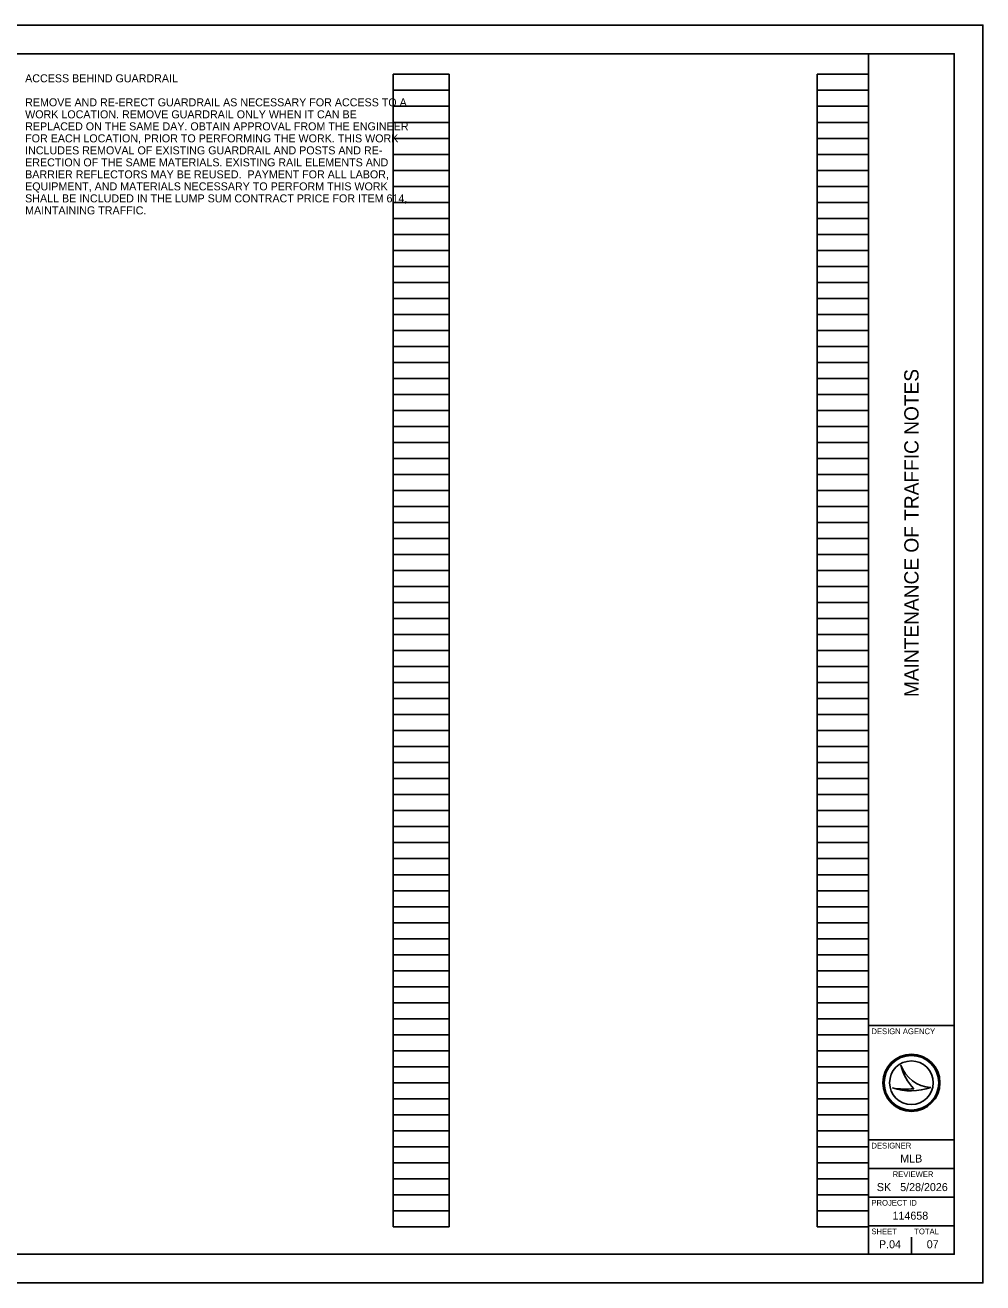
# Model space of a CAD drawing. Extents: x 0 to 34, y 0 to 22.
# Drawn here: x 17.24 to 34, y 0 to 22 of the extents above; entities that cross this region are included whole.
import ezdxf

# ---------------------------------------------------------------- set-up
doc = ezdxf.new("R2010")
doc.units = 0
for name, color, linetype in [('SH_Border', 7, 'Continuous'), ('SH_Cut_Line', 7, 'Continuous'), ('SH_Data', 7, 'Continuous'), ('SH_Text', 7, 'Continuous')]:
    doc.layers.add(name, color=color, linetype=linetype)

msp = doc.modelspace()

# ---------------------------------------------------------------- linework, layer by layer
at = {"layer": 'SH_Border'}
for p, q in [((32, 0.5), (32, 21.5)), ((32, 4.5), (33.5, 4.5)), ((32, 2.5), (33.5, 2.5)), ((32, 2), (33.5, 2)), ((32, 1.5), (33.5, 1.5)), ((32, 1), (33.5, 1))]:
    msp.add_line(p, q, dxfattribs=at)
msp.add_lwpolyline([(1.5, 21.5), (33.5, 21.5), (33.5, 0.5), (1.5, 0.5)], close=True, dxfattribs=at)
at = {"layer": 'SH_Cut_Line'}
msp.add_lwpolyline([(0, 0), (34, 0), (34, 22), (0, 22)], close=True, dxfattribs=at)
at = {"layer": 'SH_Data'}
for p, q in [((23.68, 0.98), (23.68, 21.14)), ((23.68, 21.14), (24.66, 21.14)), ((24.66, 0.98), (24.66, 21.14)), ((31.1, 0.98), (31.1, 21.14)), ((31.1, 21.14), (32, 21.14)), ((32, 0.98), (32, 21.14)), ((23.68, 20.86), (24.66, 20.86)), ((31.1, 20.86), (32, 20.86)), ((23.68, 20.58), (24.66, 20.58)), ((31.1, 20.58), (32, 20.58)), ((23.68, 20.3), (24.66, 20.3)), ((31.1, 20.3), (32, 20.3)), ((23.68, 20.02), (24.66, 20.02)), ((31.1, 20.02), (32, 20.02)), ((23.68, 19.74), (24.66, 19.74)), ((31.1, 19.74), (32, 19.74)), ((23.68, 19.46), (24.66, 19.46)), ((31.1, 19.46), (32, 19.46)), ((23.68, 19.18), (24.66, 19.18)), ((31.1, 19.18), (32, 19.18)), ((23.68, 18.9), (24.66, 18.9)), ((31.1, 18.9), (32, 18.9)), ((23.68, 18.62), (24.66, 18.62)), ((31.1, 18.62), (32, 18.62)), ((23.68, 18.34), (24.66, 18.34)), ((31.1, 18.34), (32, 18.34)), ((23.68, 18.06), (24.66, 18.06)), ((31.1, 18.06), (32, 18.06)), ((23.68, 17.78), (24.66, 17.78)), ((31.1, 17.78), (32, 17.78)), ((23.68, 17.5), (24.66, 17.5)), ((31.1, 17.5), (32, 17.5)), ((23.68, 17.22), (24.66, 17.22)), ((31.1, 17.22), (32, 17.22)), ((23.68, 16.94), (24.66, 16.94)), ((31.1, 16.94), (32, 16.94)), ((23.68, 16.66), (24.66, 16.66)), ((31.1, 16.66), (32, 16.66)), ((23.68, 16.38), (24.66, 16.38)), ((31.1, 16.38), (32, 16.38)), ((23.68, 16.1), (24.66, 16.1)), ((31.1, 16.1), (32, 16.1)), ((23.68, 15.82), (24.66, 15.82)), ((31.1, 15.82), (32, 15.82)), ((23.68, 15.54), (24.66, 15.54)), ((31.1, 15.54), (32, 15.54)), ((23.68, 15.26), (24.66, 15.26)), ((31.1, 15.26), (32, 15.26)), ((23.68, 14.98), (24.66, 14.98)), ((31.1, 14.98), (32, 14.98)), ((23.68, 14.7), (24.66, 14.7)), ((31.1, 14.7), (32, 14.7)), ((23.68, 14.42), (24.66, 14.42)), ((31.1, 14.42), (32, 14.42)), ((23.68, 14.14), (24.66, 14.14)), ((31.1, 14.14), (32, 14.14)), ((23.68, 13.86), (24.66, 13.86)), ((31.1, 13.86), (32, 13.86)), ((23.68, 13.58), (24.66, 13.58)), ((31.1, 13.58), (32, 13.58)), ((23.68, 13.3), (24.66, 13.3)), ((31.1, 13.3), (32, 13.3)), ((23.68, 13.02), (24.66, 13.02)), ((31.1, 13.02), (32, 13.02)), ((23.68, 12.74), (24.66, 12.74)), ((31.1, 12.74), (32, 12.74)), ((23.68, 12.46), (24.66, 12.46)), ((31.1, 12.46), (32, 12.46)), ((23.68, 12.18), (24.66, 12.18)), ((31.1, 12.18), (32, 12.18)), ((23.68, 11.9), (24.66, 11.9)), ((31.1, 11.9), (32, 11.9)), ((23.68, 11.62), (24.66, 11.62)), ((31.1, 11.62), (32, 11.62)), ((23.68, 11.34), (24.66, 11.34)), ((31.1, 11.34), (32, 11.34)), ((23.68, 11.06), (24.66, 11.06)), ((31.1, 11.06), (32, 11.06)), ((23.68, 10.78), (24.66, 10.78)), ((31.1, 10.78), (32, 10.78)), ((23.68, 10.5), (24.66, 10.5)), ((31.1, 10.5), (32, 10.5)), ((23.68, 10.22), (24.66, 10.22)), ((31.1, 10.22), (32, 10.22)), ((23.68, 9.94), (24.66, 9.94)), ((31.1, 9.94), (32, 9.94)), ((23.68, 9.66), (24.66, 9.66)), ((31.1, 9.66), (32, 9.66)), ((23.68, 9.38), (24.66, 9.38)), ((31.1, 9.38), (32, 9.38)), ((23.68, 9.1), (24.66, 9.1)), ((31.1, 9.1), (32, 9.1)), ((23.68, 8.82), (24.66, 8.82)), ((31.1, 8.82), (32, 8.82)), ((23.68, 8.54), (24.66, 8.54)), ((31.1, 8.54), (32, 8.54)), ((23.68, 8.26), (24.66, 8.26)), ((31.1, 8.26), (32, 8.26)), ((23.68, 7.98), (24.66, 7.98)), ((31.1, 7.98), (32, 7.98)), ((23.68, 7.7), (24.66, 7.7)), ((31.1, 7.7), (32, 7.7)), ((23.68, 7.42), (24.66, 7.42)), ((31.1, 7.42), (32, 7.42)), ((23.68, 7.14), (24.66, 7.14)), ((31.1, 7.14), (32, 7.14)), ((23.68, 6.86), (24.66, 6.86)), ((31.1, 6.86), (32, 6.86)), ((23.68, 6.58), (24.66, 6.58)), ((31.1, 6.58), (32, 6.58)), ((23.68, 6.3), (24.66, 6.3)), ((31.1, 6.3), (32, 6.3)), ((23.68, 6.02), (24.66, 6.02)), ((31.1, 6.02), (32, 6.02)), ((23.68, 5.74), (24.66, 5.74)), ((31.1, 5.74), (32, 5.74)), ((23.68, 5.46), (24.66, 5.46)), ((31.1, 5.46), (32, 5.46)), ((23.68, 5.18), (24.66, 5.18)), ((31.1, 5.18), (32, 5.18)), ((23.68, 4.9), (24.66, 4.9)), ((31.1, 4.9), (32, 4.9)), ((23.68, 4.62), (24.66, 4.62)), ((31.1, 4.62), (32, 4.62)), ((23.68, 4.34), (24.66, 4.34)), ((31.1, 4.34), (32, 4.34)), ((23.68, 4.06), (24.66, 4.06)), ((31.1, 4.06), (32, 4.06)), ((23.68, 3.78), (24.66, 3.78)), ((31.1, 3.78), (32, 3.78)), ((32.567, 3.81), (32.567, 3.81)), ((23.68, 3.5), (24.66, 3.5)), ((31.1, 3.5), (32, 3.5)), ((32.417, 3.41), (32.417, 3.41)), ((32.75, 3.5), (32.75, 3.5)), ((33.087, 3.419), (33.087, 3.419)), ((23.68, 3.22), (24.66, 3.22)), ((31.1, 3.22), (32, 3.22)), ((23.68, 2.94), (24.66, 2.94)), ((31.1, 2.94), (32, 2.94)), ((23.68, 2.66), (24.66, 2.66)), ((31.1, 2.66), (32, 2.66)), ((23.68, 2.38), (24.66, 2.38)), ((31.1, 2.38), (32, 2.38)), ((23.68, 2.1), (24.66, 2.1)), ((31.1, 2.1), (32, 2.1)), ((23.68, 1.82), (24.66, 1.82)), ((31.1, 1.82), (32, 1.82)), ((23.68, 1.54), (24.66, 1.54)), ((31.1, 1.54), (32, 1.54)), ((23.68, 1.26), (24.66, 1.26)), ((31.1, 1.26), (32, 1.26)), ((23.68, 0.98), (24.66, 0.98)), ((31.1, 0.98), (32, 0.98)), ((32.375, 0.675), (32.375, 0.675)), ((32.75, 0.5), (32.75, 0.8))]:
    msp.add_line(p, q, dxfattribs=at)
for radius in [0.5, 0.477, 0.477, 0.382]:
    msp.add_circle((32.75, 3.5), radius, dxfattribs=at)
for centre, radius, start, end in [((33.116, 3.998), 0.58, 198.9257, 198.9319), ((33.347, 3.97), 0.796, 191.6379, 191.6421), ((33.116, 3.998), 0.58, 198.9319, 267.1657), ((33.347, 3.97), 0.796, 191.6421, 226.0947), ((32.739, 4.37), 1.013, 251.4576, 290.0832), ((32.648, 4.654), 1.266, 259.4964, 259.4995), ((32.739, 4.37), 1.013, 251.4527, 251.4576), ((32.648, 4.654), 1.266, 259.4995, 276.6672)]:
    msp.add_arc(centre, radius, start, end, dxfattribs=at)

# ---------------------------------------------------------------- texts
msp.add_text('MAINTENANCE OF TRAFFIC NOTES', height=0.25, rotation=90, dxfattribs=at).set_placement((32.875, 10.247))
for s, height, p in [('DESIGN AGENCY', 0.1, (32.05, 4.35)), ('DESIGNER', 0.1, (32.05, 2.35)), ('MLB', 0.14, (32.554, 2.105)), ('REVIEWER', 0.1, (32.422, 1.85)), ('SK', 0.14, (32.145, 1.605)), ('5/28/2026', 0.14, (32.553, 1.605)), ('PROJECT ID', 0.1, (32.05, 1.35)), ('114658', 0.14, (32.419, 1.105)), ('SHEET', 0.1, (32.05, 0.85)), ('TOTAL', 0.1, (32.8, 0.85)), ('P.04', 0.14, (32.182, 0.605)), ('07', 0.14, (33.018, 0.605))]:
    msp.add_text(s, height=height, dxfattribs=at).set_placement(p)
at = {"layer": 'SH_Text'}
for s, p in [('ACCESS BEHIND GUARDRAIL', (17.24, 21)), ('REMOVE AND RE-ERECT GUARDRAIL AS NECESSARY FOR ACCESS TO A ', (17.24, 20.58)), ('WORK LOCATION. REMOVE GUARDRAIL ONLY WHEN IT CAN BE ', (17.24, 20.37)), ('REPLACED ON THE SAME DAY. OBTAIN APPROVAL FROM THE ENGINEER ', (17.24, 20.16)), ('FOR EACH LOCATION, PRIOR TO PERFORMING THE WORK. THIS WORK ', (17.24, 19.95)), ('INCLUDES REMOVAL OF EXISTING GUARDRAIL AND POSTS AND RE-', (17.24, 19.74)), ('ERECTION OF THE SAME MATERIALS. EXISTING RAIL ELEMENTS AND ', (17.24, 19.53)), ('BARRIER REFLECTORS MAY BE REUSED.  PAYMENT FOR ALL LABOR, ', (17.24, 19.32)), ('EQUIPMENT, AND MATERIALS NECESSARY TO PERFORM THIS WORK ', (17.24, 19.11)), ('SHALL BE INCLUDED IN THE LUMP SUM CONTRACT PRICE FOR ITEM 614, ', (17.24, 18.9)), ('MAINTAINING TRAFFIC.', (17.24, 18.69))]:
    msp.add_text(s, height=0.14, dxfattribs=at).set_placement(p)

doc.saveas('drawing.dxf')
